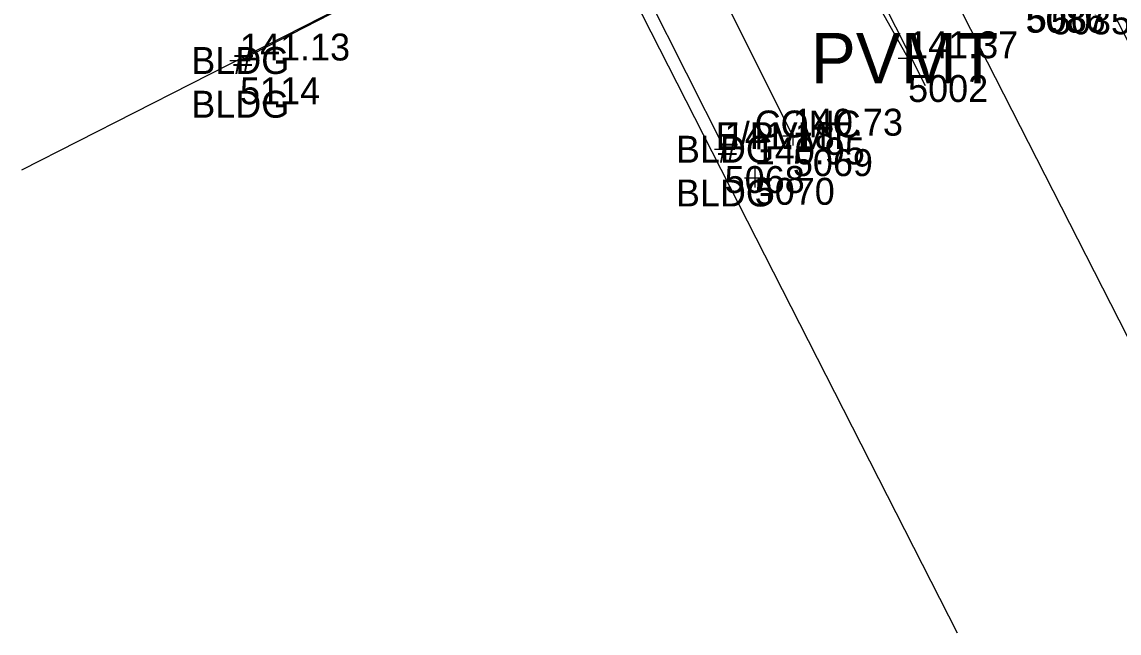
# Model space of a CAD drawing. Extents: x 13482495 to 13483389, y 311646 to 312209.
# Drawn here: x 13482568.2 to 13482698.6, y 311645.7 to 311718.3 of the extents above; entities that cross this region are included whole.
import ezdxf

# ---------------------------------------------------------------- set-up
doc = ezdxf.new("R2010")
doc.units = 0
for name, color, linetype in [('V-BLDG-OTLN', 7, 'Continuous'), ('V-DOMW-MAIN', 7, 'Continuous'), ('V-PROP-RWAY', 7, 'Continuous'), ('V-PROP-RWAY-IDEN', 7, 'Continuous'), ('V-PVMT-CNTR', 7, 'Continuous'), ('V-PVMT-ROAD', 7, 'Continuous'), ('V-PVMT-SPOT', 7, 'Continuous'), ('V-SITE-IDEN', 7, 'Continuous'), ('V-SITE-SPOT', 7, 'Continuous'), ('V-STRM-MAIN', 7, 'Continuous'), ('V-SURV-PNTS', 7, 'Continuous'), ('V-TOPO-LINE-IDEN', 7, 'Continuous')]:
    doc.layers.add(name, color=color, linetype=linetype)

msp = doc.modelspace()

# ---------------------------------------------------------------- linework, layer by layer
at = {"layer": 'V-BLDG-OTLN'}
msp.add_lwpolyline([(13482651.73, 311703.22), (13482638.08, 311730.36), (13482635.32, 311735.26), (13482630.67, 311732.54), (13482594.1, 311713.77)], dxfattribs=at)
at = {"layer": 'V-DOMW-MAIN'}
msp.add_line((13482709.69, 311661.21), (13482597.52, 311881.07), dxfattribs=at)
at = {"layer": 'V-PROP-RWAY'}
for p, q in [((13482723.95, 311668.48), (13482678.7, 311757.16)), ((13482568.17, 311700.77), (13482634.16, 311734.44)), ((13482679.43, 311645.72), (13482634.16, 311734.44))]:
    msp.add_line(p, q, dxfattribs=at)
at = {"layer": 'V-PVMT-CNTR'}
msp.add_lwpolyline([(13482673.54, 311714.04), (13482656.18, 311744.95), (13482644.2, 311768.11), (13482629.86, 311797.03), (13482611.78, 311831.96)], dxfattribs=at)
at = {"layer": 'V-PVMT-ROAD'}
msp.add_lwpolyline([(13482659.84, 311704.83), (13482645.17, 311734.1), (13482642.05, 311740.02), (13482641.56, 311740.84), (13482640.35, 311742.28), (13482638.71, 311743.59), (13482637.79, 311744.13), (13482635.83, 311744.92), (13482634.82, 311745.16), (13482633.31, 311745.24), (13482631.96, 311745.01), (13482631.08, 311744.71), (13482629.27, 311743.86), (13482589.73, 311723.31)], dxfattribs=at)
at = {"layer": 'V-PVMT-SPOT'}
for p, q in [((13482673.54, 311715.2), (13482673.54, 311712.88)), ((13482672.34, 311714.04), (13482674.74, 311714.04)), ((13482659.84, 311705.99), (13482659.84, 311703.67)), ((13482658.64, 311704.83), (13482661.04, 311704.83))]:
    msp.add_line(p, q, dxfattribs=at)
at = {"layer": 'V-SITE-SPOT'}
for p, q in [((13482592.9, 311713.77), (13482595.3, 311713.77)), ((13482594.1, 311714.93), (13482594.1, 311712.61)), ((13482651.73, 311704.38), (13482651.73, 311702.06)), ((13482650.53, 311703.22), (13482652.93, 311703.22)), ((13482655.3, 311700.98), (13482655.3, 311698.66)), ((13482654.1, 311699.82), (13482656.5, 311699.82))]:
    msp.add_line(p, q, dxfattribs=at)
at = {"layer": 'V-STRM-MAIN'}
msp.add_line((13482675.59, 311710.76), (13482620.58, 311820.25), dxfattribs=at)

# ---------------------------------------------------------------- texts
at = {"layer": 'V-PROP-RWAY-IDEN'}
msp.add_text('R.O.W. LINE', height=3.2, rotation=117.0313, dxfattribs=at).set_placement((13482706.97, 311712.32))
at = {"layer": 'V-PVMT-SPOT'}
for s, p in [('141.37', (13482673.54, 311714.04)), ('140.73', (13482659.84, 311704.83))]:
    msp.add_text(s, height=3.2, dxfattribs=at).set_placement(p)
at = {"layer": 'V-SITE-IDEN'}
msp.add_text('CONC', height=3.2, dxfattribs=at).set_placement((13482655.3, 311704.62))
at = {"layer": 'V-SITE-SPOT'}
for s, p in [('141.13', (13482594.1, 311713.77)), ('141.18', (13482651.73, 311703.22)), ('140.95', (13482655.3, 311701.42))]:
    msp.add_text(s, height=3.2, dxfattribs=at).set_placement(p)
at = {"layer": 'V-SURV-PNTS'}
for s, p in [('5086', (13482687.51, 311717.07)), ('5087', (13482687.65, 311717.14)), ('5035', (13482690.52, 311716.88)), ('5114', (13482594.1, 311708.57)), ('5002', (13482673.54, 311708.84)), ('5069', (13482659.84, 311700.03)), ('5068', (13482651.73, 311698.02)), ('5070', (13482655.3, 311696.62))]:
    msp.add_text(s, height=3.2, dxfattribs=at).set_placement(p)
at = {"layer": 'V-TOPO-LINE-IDEN'}
for s, height, p in [('PVMT', 6, (13482661.97, 311711.04)), ('BLDG', 3.2, (13482588.3, 311712.17)), ('#', 3.2, (13482593.28, 311712.17)), ('BLDG', 3.2, (13482588.3, 311706.97)), ('E/PVMT', 3.2, (13482650.66, 311703.23)), ('BLDG', 3.2, (13482645.93, 311701.62)), ('#', 3.2, (13482650.91, 311701.62)), ('BLDG', 3.2, (13482645.93, 311696.42))]:
    msp.add_text(s, height=height, dxfattribs=at).set_placement(p)

doc.saveas('drawing.dxf')
